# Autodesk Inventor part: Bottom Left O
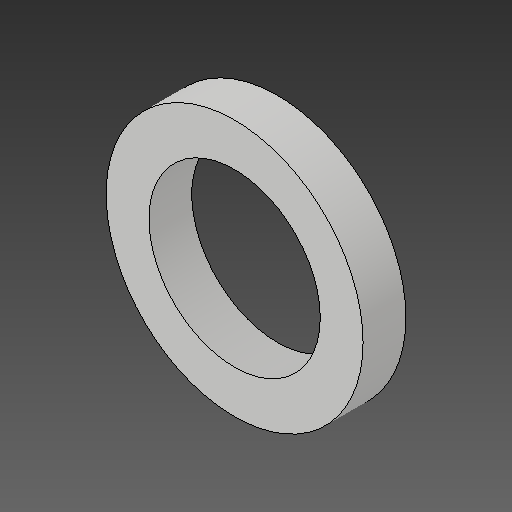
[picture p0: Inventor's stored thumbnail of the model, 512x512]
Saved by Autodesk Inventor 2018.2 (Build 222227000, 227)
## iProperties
Created: 2018-03
Part Number: Bottom Left O
Material: Generic
Document SubType Name: Modeling
Designer: PeterMaxwell-Stewart
Mass: 1.9635 g
Surface Area: 15.708 cm^2
Volume: 1.9635 cm^3
Density: 1 g/cm^3
Appearance: Default
Author: PeterMaxwell-Stewart
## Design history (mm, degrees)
derived "O's and X's.ipt"
feature "Bottom Left O::O's and X's.ipt" dims "d0" = 10
tag "TaggingFeature1"
body "Solid1"
